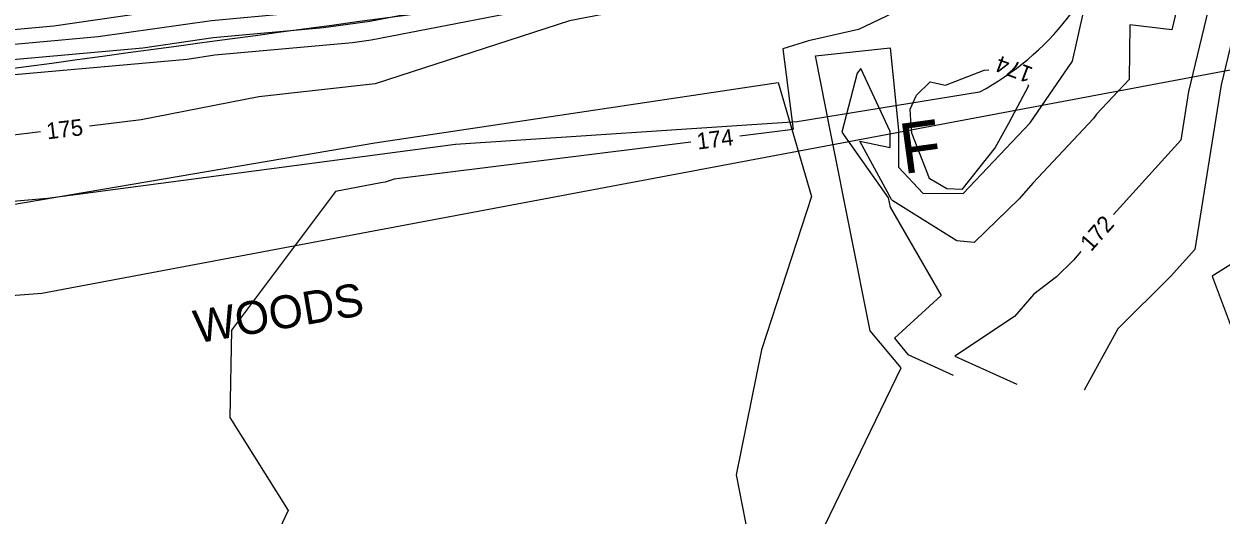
# Model space of a CAD drawing. Extents: x 2086416 to 2115205, y 575507 to 632762.
# Drawn here: x 2111920.5 to 2112066, y 581620.8 to 581680.5 of the extents above; entities that cross this region are included whole.
import ezdxf

# ---------------------------------------------------------------- set-up
doc = ezdxf.new("R2010")
doc.units = 0
for name, color, linetype in [('DTM Contours Major', 7, 'Continuous'), ('DTM Contours Major Text', 7, 'Continuous'), ('DTM Contours Minor', 7, 'Continuous'), ('DTM Contours Minor Text', 7, 'Continuous'), ('Exist Hydro Stream or Body of Water', 7, 'Continuous'), ('Exist Hydrographic FEMA Cross Section', 7, 'Continuous'), ('Exist Right of Way Line', 7, 'Continuous'), ('Exist Vegetation Woods Line', 7, 'Continuous'), ('Exist Vegetation Woods Line Text', 7, 'Continuous'), ('Prop SS Fill Line', 7, 'Continuous'), ('Prop SS Fill Text', 7, 'Continuous')]:
    doc.layers.add(name, color=color, linetype=linetype)

msp = doc.modelspace()

# ---------------------------------------------------------------- linework, layer by layer
at = {"layer": 'DTM Contours Major'}
for points in [[(2112026.02, 581688.95), (2112012.75, 581685.87), (2112011.72, 581685.68), (2111992.43, 581681.95), (2111992.08, 581681.89), (2111986.82, 581680.87), (2111963.21, 581673.22), (2111949.06, 581671.62), (2111934.77, 581668.82), (2111928.47, 581668.07)], [(2111922.51, 581667.36), (2111914.6, 581666.41), (2111904.37, 581661.02), (2111870.64, 581651.43), (2111865.11, 581649.26), (2111862.98, 581649.41), (2111825.91, 581645.06)]]:
    msp.add_lwpolyline(points, dxfattribs=at)
at = {"layer": 'DTM Contours Minor'}
for points in [[(2112099.58, 581721.47), (2112099.78, 581716.48), (2112098.96, 581715.12), (2112098.92, 581714.21), (2112096.91, 581702.43), (2112096.94, 581702.35), (2112096.95, 581702.25), (2112096.93, 581702.06), (2112096.43, 581701.23), (2112087.62, 581683.65), (2112083.11, 581676.95), (2112080.12, 581659.33), (2112072.6, 581654.59), (2112064.96, 581649.82), (2112068.33, 581640.74)], [(2112061.21, 581719.46), (2112062.6, 581717.03), (2112064.76, 581713.69), (2112066.89, 581710.24), (2112070.14, 581700.28), (2112072.84, 581697.24), (2112070.63, 581692.11), (2112066.05, 581673.08), (2112062.82, 581653.08), (2112059.86, 581649.8), (2112053.49, 581643.44), (2112049.37, 581635.99)], [(2112030.61, 581696.21), (2112025.42, 581695.63), (2112012.04, 581692.52), (2112001.8, 581690.61), (2111991.88, 581688.69), (2111977.03, 581685.93), (2111962.38, 581683.09), (2111953.41, 581681.8), (2111943.32, 581680.88), (2111929.54, 581678.91), (2111913.53, 581677.46), (2111903.25, 581675.52), (2111889.81, 581672.88), (2111877.32, 581670.52), (2111860.03, 581667.11), (2111854.99, 581666.74), (2111846.39, 581665.97), (2111835.52, 581665.17), (2111833.31, 581664.98)], [(2112067.49, 581694.94), (2112064.51, 581682.38), (2112062.08, 581672.28), (2112061.12, 581666.37), (2112052.96, 581657.34)], [(2112031.77, 581694.58), (2112029.72, 581694.35), (2112012.28, 581690.31), (2112005.11, 581688.97), (2111992.06, 581686.45), (2111982.05, 581684.58), (2111962.56, 581680.8), (2111956.92, 581679.99), (2111943.51, 581678.78), (2111934.94, 581677.55), (2111913.68, 581675.63), (2111907.39, 581674.44), (2111889.3, 581670.89), (2111883.08, 581669.72), (2111859.35, 581665.03), (2111858.2, 581664.94), (2111846.44, 581663.89), (2111842.37, 581663.59), (2111834.55, 581662.91)], [(2112032.78, 581692.79), (2112012.51, 581688.09), (2112008.41, 581687.33), (2111992.25, 581684.2), (2111987.07, 581683.23), (2111962.73, 581678.52), (2111960.43, 581678.19), (2111943.7, 581676.67), (2111940.33, 581676.18), (2111913.84, 581673.8), (2111911.52, 581673.36), (2111889.18, 581668.98), (2111888.94, 581668.85), (2111888.64, 581668.76), (2111861.62, 581658.14), (2111851.19, 581658.87), (2111839.99, 581657.56), (2111837.2, 581658.34)], [(2112062.95, 581692.04), (2112060.03, 581679.77), (2112054.92, 581680.38), (2112054.84, 581673.74), (2112050.88, 581669.5), (2112050.51, 581669.01), (2112043.14, 581661.15), (2112041.47, 581659.21), (2112036.01, 581653.93), (2112033.92, 581654.13), (2112026.14, 581658.98), (2112025.97, 581659.15), (2112022.13, 581666.23), (2112025.82, 581665.48), (2112025.79, 581667.42), (2112022.23, 581675.07), (2112021.78, 581674.52), (2112019.93, 581667.34), (2112025.55, 581659.33), (2112025.8, 581658.2), (2112031.99, 581647.48), (2112026.31, 581642.3), (2112027.95, 581640.3), (2112033.47, 581637.79)], [(2112038.81, 581687.86), (2112021.96, 581679.82), (2112015.88, 581678.42), (2112012.75, 581677.44), (2112014.01, 581667.67), (2112007.52, 581666.86)], [(2111766.73, 581655.75), (2111766.93, 581655.79), (2111772.78, 581656.67), (2111784.88, 581657.27), (2111787.5, 581655.85), (2111788.16, 581659.18), (2111790.87, 581660.53), (2111806.83, 581663.96), (2111816.47, 581665.68), (2111828.67, 581666.75), (2111846.33, 581668.05), (2111851.77, 581668.53), (2111860.72, 581669.19), (2111871.55, 581671.33), (2111890.31, 581674.87), (2111899.11, 581676.6), (2111913.37, 581679.3), (2111924.15, 581680.27), (2111943.14, 581682.99), (2111949.9, 581683.61), (2111961.23, 581685.23)], [(2112032.69, 581660.45), (2112030.64, 581661.66), (2112030.53, 581661.77), (2112030.38, 581662.21), (2112028.42, 581667.21), (2112028.36, 581668.11), (2112028.22, 581670.14), (2112029, 581671.84), (2112030.65, 581673.44), (2112032.52, 581673.05), (2112037.22, 581674.88), (2112037.81, 581674.89)], [(2112042.55, 581673.12), (2112042.62, 581672.95), (2112040.17, 581668.38), (2112038.56, 581665.46), (2112034.52, 581660.38), (2112032.69, 581660.45)], [(2112001.57, 581666.12), (2111965.52, 581661.61), (2111964.4, 581661.24), (2111963.9, 581661.19), (2111958.38, 581660.11), (2111945.74, 581643.25), (2111945.53, 581632.64), (2111952.64, 581621.35), (2111948.73, 581613.13), (2111963.74, 581611.46), (2111970.42, 581606.19), (2111976.09, 581595.16), (2111984.65, 581581.25), (2111984.7, 581578.65), (2111987.39, 581578.17), (2111998.82, 581581.21), (2112008.29, 581584.73), (2112005.23, 581606.22), (2112005.78, 581606.97)], [(2112048.99, 581652.84), (2112048.07, 581651.78), (2112046.04, 581649.74), (2112043.25, 581647.63), (2112040.93, 581644.92), (2112033.68, 581640.1), (2112041.2, 581636.69)]]:
    msp.add_lwpolyline(points, dxfattribs=at)
at = {"layer": 'Exist Hydro Stream or Body of Water'}
for points in [[(2112027.13, 581638.7), (2112023.35, 581643.17), (2112018.58, 581667.17), (2112016.71, 581676.59), (2112025.79, 581677.58), (2112026.82, 581667.59), (2112026.82, 581663.09), (2112029.79, 581659.93), (2112034.68, 581659.86), (2112042.82, 581668.45), (2112047.95, 581675.95), (2112050.49, 581687.19), (2112059.54, 581689.87), (2112059.94, 581700.98)], [(2112026.79, 581556.19), (2112027.99, 581568.85), (2112025.16, 581584.18), (2112023.21, 581604.37), (2112017.27, 581618.27), (2112027.13, 581638.7)]]:
    msp.add_lwpolyline(points, dxfattribs=at)
at = {"layer": 'Exist Hydrographic FEMA Cross Section'}
msp.add_lwpolyline([(2112201.88, 581700.22), (2111922.67, 581647.71), (2111776.13, 581636.5), (2111658.78, 581615.59), (2111477.28, 581602.23)], dxfattribs=at)
at = {"layer": 'Exist Right of Way Line'}
msp.add_arc((2119136.65, 528602.9), 53560.67, 97.642388, 97.856215, dxfattribs=at)
at = {"layer": 'Exist Vegetation Woods Line'}
for points in [[(2111785.51, 581656), (2111806.71, 581641.4), (2111833.87, 581646.25), (2111866.92, 581639.44), (2111902.2, 581655.66), (2111963.16, 581666.03), (2112012.17, 581673.36), (2112016.22, 581659.52)], [(2112016.22, 581659.52), (2112010.15, 581640.89), (2112007.07, 581625.66), (2112011.47, 581603.31), (2112014.66, 581580.91), (2112013.34, 581563.73), (2112012.63, 581538.51), (2112010.71, 581519.35), (2112013.56, 581494.84), (2112014.97, 581481.49), (2112022.73, 581466.4), (2112037.51, 581453.75), (2112050.78, 581446.7), (2112062.82, 581439.28), (2112065.18, 581428.19)]]:
    msp.add_lwpolyline(points, dxfattribs=at)
at = {"layer": 'Prop SS Fill Line'}
for p, q in [((2112014.49, 581668.64), (2112036.68, 581672.23)), ((2111972.95, 581665.89), (2112014.49, 581668.64)), ((2111923.38, 581659.31), (2111972.95, 581665.89)), ((2111873.52, 581654.92), (2111923.38, 581659.31))]:
    msp.add_line(p, q, dxfattribs=at)
msp.add_arc((2112020.67, 581702.15), 33.94, 298.1531, 345.6062, dxfattribs=at)

# ---------------------------------------------------------------- texts
at = {"layer": 'DTM Contours Major Text'}
msp.add_text('175', height=2, rotation=6.8056, dxfattribs=at).set_placement((2111923.35, 581666.45))
at = {"layer": 'DTM Contours Minor Text'}
for s, rotation, p in [('174', 159.5009, (2112043.29, 581675.12)), ('174', 7.1325, (2112002.41, 581665.21)), ('172', 48.6477, (2112050.22, 581652.72))]:
    msp.add_text(s, height=2, rotation=rotation, dxfattribs=at).set_placement(p)
at = {"layer": 'Exist Vegetation Woods Line Text'}
msp.add_text('WOODS', height=4, rotation=9.6237, dxfattribs=at).set_placement((2111941.53, 581641.65))
at = {"layer": 'Prop SS Fill Text'}
msp.add_text('F', height=6.1, rotation=7.771, dxfattribs=at).set_placement((2112027.4, 581662.23))

doc.saveas('drawing.dxf')
